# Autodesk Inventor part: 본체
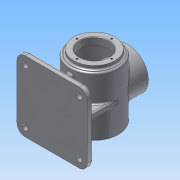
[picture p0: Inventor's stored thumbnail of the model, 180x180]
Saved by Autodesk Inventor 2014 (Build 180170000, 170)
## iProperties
Created: 2015-07
Part Number: 본체
Material: 알루미늄 6061
Document SubType Name: Modeling
Designer: nert
Density: 2.71 g/cm^3
Appearance: 알루미늄 - 평지
Mass: 1277.62 g
Surface Area: 1267.64 cm^2
Volume: 471.447 cm^3
Author: nert
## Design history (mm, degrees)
sketch "스케치1"
  geometry: L1 (-65, -65)-(65, -65); L2 (65, -65)-(65, 65); L3 (65, 65)-(-65, 65); L4 (-65, 65)-(-65, -65); L5 (-65, -65)-(65, 65); L6 (65, -65)-(-65, 65); 1 further point
  constraints: 12 end point, 2 midpoint, 2 parallel, 1 horizontal, 1 perpendicular
  dimensions: "d0" = 130 distance of L3.end L2.end; "d1" = 130 distance of L2.end L1.end
extrude "돌출1" new body sketch "스케치1" distance "d2" = 10; taper "d3" = 0 deg
sketch "스케치2"
  geometry: L1 (-65, 0)-(65, 0) reference; C1 r 45 at (0, 78); 2 further points
  constraints: 1 centre point, 1 midpoint, 1 vertical alignment
  dimensions: "d4" = 90 diameter of C1; "d12" = 78 distance from line of L1 C1.centre
extrude "돌출2" join sketch "스케치2" stored distance "d5" = 110; taper "d6" = 0 deg
sketch "스케치3"
  geometry: C1 r 45 at (0, 0) reference; C2 r 38 at (0, 0); 1 further point
  constraints: 1 centre point, 1 coincident
  dimensions: "d7" = 76 diameter of C2
extrude "돌출3" join sketch "스케치3" distance "d8" = 7; taper "d9" = 0 deg
node "작업 평면1"
sketch "스케치4"
  geometry: L1 (-45, -55)-(45, -55) reference; C1 r 38 at (0, 0); 1 further point
  constraints: 1 centre point, 1 coincident
  dimensions: "d11" = 76 diameter of C1
extrude "돌출4" join sketch "스케치4" stored distance "d13" = 7; taper "d14" = 0 deg
sketch "스케치5"
  geometry: L1 (65, -65)-(65, 65) reference; L2 (-5, 45)-(-5, -45); L3 (-5, -45)-(5, -45); L4 (5, -45)-(5, 45); L5 (5, 45)-(-5, 45); L6 (-45, 5)-(-45, -5); L7 (-45, -5)-(45, -5); L8 (45, -5)-(45, 5); L9 (45, 5)-(-45, 5); 5 further points
  constraints: 16 end point, 4 midpoint, 3 parallel, 3 perpendicular, 2 horizontal alignment, 2 vertical alignment
  dimensions: "d19" = 90 distance of L2.start L2.end; "d20" = 10 distance of L2.end L3.end; "d21" = 90 distance of L3.end L4.end; "d22" = 10 distance of L6.start L6.end; "d23" = 90 distance of L6.end L7.end; "d24" = 10 distance of L7.end L8.end
extrude "돌출5" join sketch "스케치5" stored distance "d25" = 7; taper "d26" = 0 deg
sketch "스케치6"
  geometry: C1 r 38 at (0, 0) reference; 1 further point
hole "구멍1" sketch "스케치6" at (0, 0) diameter "d27" = 54; stored, may be unused: countersink angle "d31" = 90 deg, drill point angle "d33" = 0 deg; dims "d28" = 6, "d29" = 4, "d30" = 2, "d32" = 14
node "작업 평면2"
sketch "스케치7"
  geometry: C1 r 45 at (0, 0) reference; C2 r 40 at (0, 0); 1 further point
  constraints: 1 centre point, 1 coincident
  dimensions: "d35" = 80 diameter of C2
extrude "돌출6" cut sketch "스케치7" distance "d36" = 96; taper "d37" = 0 deg
sketch "스케치8"
  geometry: C1 r 38 at (0, 0) reference
hole "구멍2" sketch "스케치8" at (0, 0) diameter "d38" = 54; stored, may be unused: countersink angle "d42" = 90 deg, drill point angle "d44" = 0 deg; dims "d39" = 6, "d40" = 4, "d41" = 2, "d43" = 54
sketch "스케치9"
  geometry: C1 r 5 at (50, -50); C2 r 7.5 at (50, -50); 1 further point
  constraints: 2 centre point, 1 coincident
  dimensions: "d46" = 10 diameter of C1; "d47" = 50 horizontal distance of C1.centre point (0, 0); "d48" = 50 horizontal distance of point (0, 0) C1.centre; "d50" = 15 diameter of C2
extrude "돌출7" join sketch "스케치9" distance "d51" = 3; taper "d52" = 0 deg
sketch "스케치10"
  geometry: C1 r 7.5 at (0, 0) reference; C2 r 5 at (0, 0); 1 further point
  constraints: 1 centre point, 1 coincident
  dimensions: "d53" = 10 diameter of C2
extrude "돌출8" cut sketch "스케치10" stored distance "d54" = 3; taper "d55" = 0 deg
sketch "스케치11"
  geometry: C1 r 27 at (0, 0) reference; 2 further points
  constraints: 1 vertical alignment
  dimensions: "d56" = 32 distance of C1.centre point (0, 32)
hole "구멍3" sketch "스케치11" at (0, 32) diameter "d57" = 3.242; stored, may be unused: countersink angle "d61" = 90 deg, drill point angle "d63" = 118 deg; dims "d58" = 8, "d59" = 4, "d60" = 2, "d62" = 10
sketch "스케치12"
  geometry: C1 r 27 at (0, 0) reference; 1 further point
  constraints: 1 vertical alignment
  dimensions: "d64" = 32 distance of C1.centre point (0, 32)
hole "구멍4" sketch "스케치12" at (0, 32) diameter "d65" = 3.242; stored, may be unused: countersink angle "d69" = 90 deg, drill point angle "d71" = 118 deg; dims "d66" = 8, "d67" = 4, "d68" = 2, "d70" = 10
chamfer "모따기1" distance "d72" = 1; stored, may be unused: second distance "d73" = 2, angle "d74" = 45 deg
fillet "모깎기1" dims "d81" = 15
fillet "모깎기2" dims "d82" = 3
fillet "모깎기3" dims "d83" = 3
fillet "모깎기4" dims "d90" = 3
fillet "모깎기5" dims "d91" = 3
fillet "모깎기6" dims "d92" = 3
fillet "모깎기7" dims "d93" = 3
chamfer "모따기2" distance "d94" = 1; stored, may be unused: second distance "d95" = 2, angle "d96" = 45 deg
fillet "모깎기8" dims "d97" = 3
fillet "모깎기9" dims "d98" = 3
fillet "모깎기10" dims "d99" = 3
sketch "스케치13"
  geometry: L1 (-24.887, 3.602)-(24.887, 3.602); L2 (24.887, 3.602)-(24.887, -3.602); L3 (24.887, -3.602)-(-24.887, -3.602); L4 (-24.887, -3.602)-(-24.887, 3.602); C1 r 42 at (0, 0) reference; 3 further points
  constraints: 2 midpoint, 1 horizontal alignment, 1 vertical alignment, 2 other
feature "엠보싱1" sketch "스케치13" dims "d100" = 0.5, "d101" = 0
fillet "모깎기11" dims "d102" = 3
node "솔리드1"
pattern_circular "원형 패턴1" dims angle "d76" = 360 deg
pattern_circular "원형 패턴2" dims angle "d79" = 360 deg
pattern_linear "직사각형 패턴1"
other parameters: "d34" = -7
